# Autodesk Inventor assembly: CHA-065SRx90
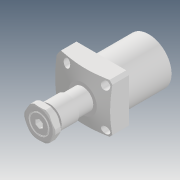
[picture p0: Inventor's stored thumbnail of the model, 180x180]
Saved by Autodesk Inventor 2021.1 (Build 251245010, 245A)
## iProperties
Created: 2019-05
Part Number: CHA-065SRx90
Description: STEP AP203
Document SubType Name: Assembly
Designer: user
Title: CHA-065SRx90.STEP
Revision Number: ÈÎºÎ
Sending System: SolidWorks 2017
Preprocessor: SwSTEP 2.0
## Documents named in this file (5)
- D:\Vault_2016\Projekty\Clamptek\Hydraulic\CHA\CHA\CHA-065\Inventor\CHA-065SRx90\CHA-065SRx90.iam
- D:\Vault_2016\Projekty\Clamptek\Hydraulic\CHA\CHA\CHA-065\Inventor\CHA-065SRx90\CHA-065BT.ipt
- D:\Vault_2016\Projekty\Clamptek\Hydraulic\CHA\CHA\CHA-065\Inventor\CHA-065SRx90\CHA-065S»îÈû¸Ë.ipt
- D:\Vault_2016\Projekty\Clamptek\Hydraulic\CHA\CHA\CHA-065\Inventor\CHA-065SRx90\CHA-065S×¶Ì×.ipt
- D:\Vault_2016\Projekty\Clamptek\Hydraulic\CHA\CHA\CHA-065\Inventor\CHA-065SRx90\CHA-065ÂÝÄ¸.ipt
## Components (4 placed, 4 different names)
1. CHA-065BT_1
2. CHA-065S»îÈû¸Ë_2
3. CHA-065S×¶Ì×_3
4. CHA-065ÂÝÄ¸_4
